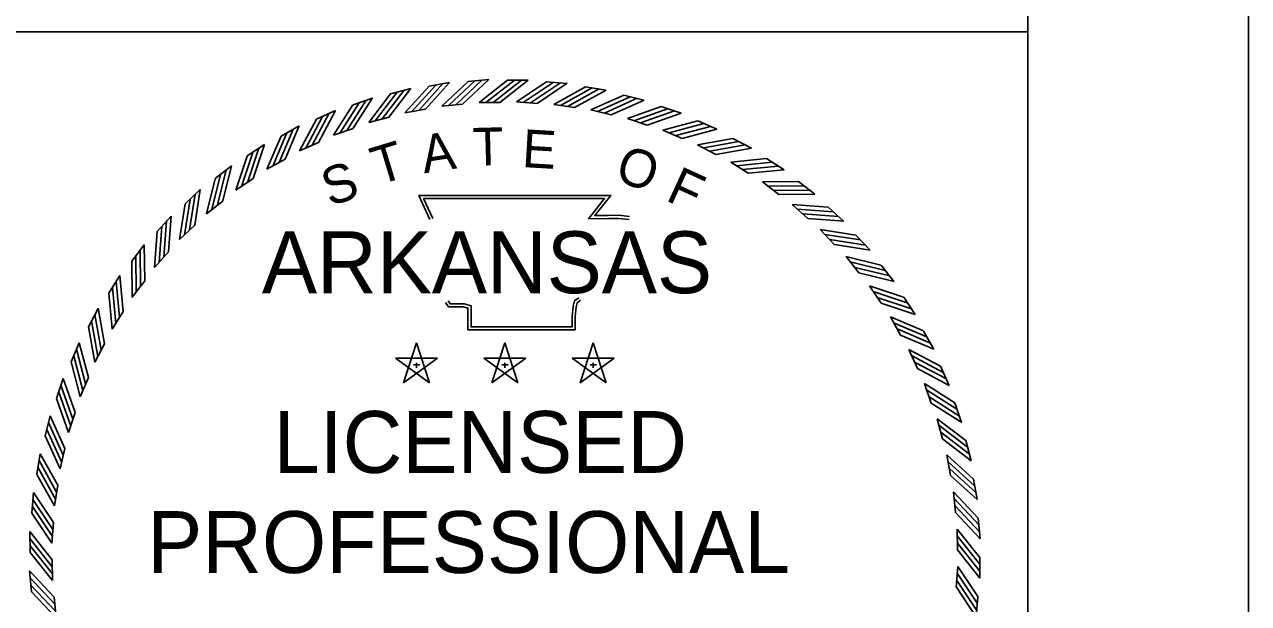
# Model space of a CAD drawing. Extents: x 0 to 1228740, y 0 to 152440.
# Drawn here: x 30.801 to 34, y 18.649 to 20.162 of the extents above; entities that cross this region are included whole.
import ezdxf

# ---------------------------------------------------------------- set-up
doc = ezdxf.new("R2010")
doc.units = 0
doc.layers.add('R_Border', color=7, linetype='Continuous')
doc.layers.add('STAMP', color=7, linetype='Continuous')

msp = doc.modelspace()

# ---------------------------------------------------------------- linework, layer by layer
at = {"layer": 'R_Border'}
for p, q in [((33.4231, 0.5768), (33.4231, 21.4232)), ((29.1131, 20.1432), (33.4231, 20.1432))]:
    msp.add_line(p, q, dxfattribs=at)
msp.add_lwpolyline([(33.9999, 22), (0, 22), (0, 0), (33.9999, 0)], close=True, dxfattribs=at)
at = {"layer": 'STAMP'}
for p, q in [((31.7579, 19.981), (31.8105, 19.9948)), ((31.8584, 20.0015), (31.912, 20.0109)), ((31.9602, 20.0137), (32.0144, 20.0186)), ((32.0633, 20.0167), (32.1177, 20.0167)), ((32.1652, 20.0126), (32.2194, 20.0086)), ((32.2669, 19.9994), (32.3206, 19.9909)), ((31.6595, 19.9522), (31.7108, 19.9703)), ((32.3671, 19.9778), (32.42, 19.965)), ((31.5637, 19.9154), (31.6134, 19.9377)), ((31.7953, 19.9316), (31.849, 19.941)), ((31.8916, 19.9492), (31.9459, 19.9542)), ((31.989, 19.9588), (32.0435, 19.9588)), ((32.0869, 19.9603), (32.1413, 19.9563)), ((32.1845, 19.9538), (32.2384, 19.9453)), ((32.2813, 19.9392), (32.3343, 19.9263)), ((32.4653, 19.9481), (32.5169, 19.9309)), ((31.7008, 19.9061), (31.7536, 19.9199)), ((32.3766, 19.9166), (32.4283, 19.8994)), ((32.5606, 19.9103), (32.6107, 19.8889)), ((31.4714, 19.8708), (31.519, 19.8972)), ((31.6088, 19.8729), (31.6602, 19.891)), ((32.4696, 19.8863), (32.5198, 19.8648)), ((31.383, 19.8188), (31.4283, 19.849)), ((31.5198, 19.8321), (31.5695, 19.8545)), ((32.5598, 19.8484), (32.608, 19.8229)), ((32.6526, 19.8648), (32.7006, 19.8393)), ((31.4344, 19.7842), (31.4821, 19.8106)), ((32.6466, 19.8031), (32.6926, 19.7737)), ((32.7404, 19.8119), (32.7862, 19.7825)), ((31.2992, 19.7596), (31.3419, 19.7934)), ((31.3533, 19.7294), (31.3987, 19.7597)), ((32.7294, 19.7509), (32.7727, 19.7178)), ((32.8235, 19.7518), (32.8668, 19.7188)), ((31.2206, 19.6937), (31.2603, 19.7309)), ((31.277, 19.6681), (31.3198, 19.702)), ((32.8076, 19.692), (32.848, 19.6554)), ((32.9015, 19.6851), (32.9418, 19.6487)), ((31.1477, 19.6216), (31.1842, 19.6619)), ((31.2061, 19.6007), (31.2459, 19.638)), ((32.8806, 19.6268), (32.9179, 19.587)), ((32.9736, 19.6123), (33.0108, 19.5726)), ((31.0811, 19.5437), (31.1141, 19.5869)), ((31.1409, 19.5277), (31.1775, 19.5681)), ((32.948, 19.5558), (32.9819, 19.5131)), ((33.0395, 19.5337), (33.0733, 19.491)), ((31.021, 19.4605), (31.0504, 19.5063)), ((31.082, 19.4495), (31.1151, 19.4928)), ((33.0093, 19.4796), (33.0396, 19.4342)), ((30.9681, 19.3727), (30.9935, 19.4207)), ((33.0987, 19.4499), (33.1288, 19.4046)), ((31.0298, 19.3667), (31.0592, 19.4127)), ((33.0641, 19.3985), (33.0905, 19.3507)), ((33.1507, 19.3615), (33.1771, 19.3139)), ((30.9226, 19.2807), (30.944, 19.3308)), ((30.9845, 19.28), (31.01, 19.3281)), ((31.8255, 19.3302), (31.7915, 19.2258)), ((31.8594, 19.2258), (31.8256, 19.3303)), ((32.0563, 19.3302), (32.0222, 19.2258)), ((32.0902, 19.2258), (32.0564, 19.3303)), ((32.2871, 19.3302), (32.253, 19.2258)), ((32.321, 19.2258), (32.2871, 19.3303)), ((31.8804, 19.2904), (31.7705, 19.2905)), ((32.1112, 19.2904), (32.0013, 19.2905)), ((32.3419, 19.2904), (32.2321, 19.2905)), ((33.112, 19.3131), (33.1344, 19.2634)), ((31.7706, 19.2904), (31.8594, 19.2257)), ((31.7916, 19.2258), (31.8805, 19.2903)), ((31.8177, 19.2728), (31.834, 19.2728)), ((31.8256, 19.2787), (31.8256, 19.2649)), ((32.0014, 19.2904), (32.0902, 19.2257)), ((32.0224, 19.2258), (32.1113, 19.2903)), ((32.0485, 19.2728), (32.0648, 19.2728)), ((32.0564, 19.2787), (32.0564, 19.2649)), ((32.2322, 19.2904), (32.321, 19.2257)), ((32.2532, 19.2258), (32.3421, 19.2903)), ((32.2793, 19.2728), (32.2956, 19.2728)), ((32.2872, 19.2787), (32.2872, 19.2649)), ((33.1953, 19.2692), (33.2176, 19.2195)), ((30.8848, 19.1854), (30.902, 19.237)), ((30.9466, 19.1897), (30.9681, 19.2399)), ((33.1528, 19.2241), (33.1709, 19.1727)), ((33.2321, 19.1734), (33.2502, 19.1221)), ((30.855, 19.0873), (30.8679, 19.1401)), ((30.9163, 19.0967), (30.9335, 19.1484)), ((33.186, 19.1321), (33.1998, 19.0793)), ((33.2608, 19.075), (33.2747, 19.0224)), ((30.8335, 18.987), (30.8419, 19.0407)), ((30.8937, 19.0014), (30.9066, 19.0544)), ((33.2115, 19.0376), (33.2209, 18.9839)), ((33.2814, 18.9745), (33.2908, 18.9209)), ((30.8203, 18.8853), (30.8243, 18.9395)), ((30.8791, 18.9046), (30.8876, 18.9585)), ((33.2291, 18.9413), (33.2341, 18.887)), ((30.8726, 18.807), (30.8766, 18.8614)), ((33.2387, 18.8439), (33.2392, 18.7893)), ((33.2936, 18.8727), (33.2985, 18.8185)), ((30.8155, 18.7828), (30.815, 18.8372)), ((30.8741, 18.7091), (30.8736, 18.7637)), ((33.2973, 18.7702), (33.2978, 18.7158)), ((30.8192, 18.6803), (30.8142, 18.7345)), ((33.2402, 18.746), (33.2362, 18.6916)), ((30.8837, 18.6117), (30.8787, 18.666)), ((33.2925, 18.6677), (33.2885, 18.6135))]:
    msp.add_line(p, q, dxfattribs=at)
for points in [[(31.7535, 19.92), (31.8106, 19.9948)], [(31.7953, 19.9315), (31.8583, 20.0014)], [(31.8126, 19.9344), (31.8756, 20.0043)], [(31.8311, 19.9381), (31.8941, 20.008)], [(31.849, 19.9411), (31.912, 20.011)], [(31.8916, 19.9491), (31.9602, 20.0136)], [(31.909, 19.9506), (31.9776, 20.015)], [(31.9278, 19.9527), (31.9964, 20.0172)], [(31.9458, 19.9542), (32.0145, 20.0187)], [(31.9889, 19.9587), (32.0632, 20.0166)], [(32.0065, 19.9586), (32.0807, 20.0165)], [(32.0254, 19.959), (32.0996, 20.0169)], [(32.0435, 19.9588), (32.1177, 20.0167)], [(32.0868, 19.9603), (32.1651, 20.0126)], [(32.1043, 19.9588), (32.1825, 20.0111)], [(32.1231, 19.9579), (32.2014, 20.0101)], [(32.1412, 19.9564), (32.2195, 20.0087)], [(32.1845, 19.9537), (32.2668, 19.9994)], [(32.2017, 19.9508), (32.2841, 19.9965)], [(31.643, 19.8852), (31.6937, 19.9645)], [(31.6601, 19.8911), (31.7108, 19.9704)], [(31.7008, 19.906), (31.7579, 19.9809)], [(31.7178, 19.9103), (31.7748, 19.9852)], [(31.7359, 19.9155), (31.793, 19.9904)], [(32.2205, 19.9483), (32.3028, 19.994)], [(32.2383, 19.9453), (32.3207, 19.991)], [(32.2812, 19.9391), (32.3671, 19.9778)], [(32.2982, 19.9348), (32.384, 19.9735)], [(32.3167, 19.9308), (32.4025, 19.9695)], [(32.3342, 19.9263), (32.4201, 19.965)], [(31.5528, 19.8472), (31.5968, 19.9305)], [(31.5694, 19.8545), (31.6134, 19.9378)], [(31.6087, 19.8728), (31.6594, 19.9521)], [(31.6253, 19.8785), (31.676, 19.9578)], [(32.3765, 19.9166), (32.4652, 19.9481)], [(32.393, 19.9109), (32.4818, 19.9424)], [(32.4111, 19.9053), (32.4998, 19.9368)], [(32.4282, 19.8994), (32.517, 19.9309)], [(31.5197, 19.8321), (31.5637, 19.9153)], [(31.5358, 19.8391), (31.5797, 19.9224)], [(32.4695, 19.8863), (32.5606, 19.9103)], [(32.4856, 19.8792), (32.5766, 19.9033)], [(31.4344, 19.7842), (31.4713, 19.8707)], [(31.4498, 19.7925), (31.4867, 19.8791)], [(31.4661, 19.802), (31.5031, 19.8886)], [(31.4821, 19.8106), (31.519, 19.8972)], [(32.5031, 19.8722), (32.5941, 19.8962)], [(32.5197, 19.8649), (32.6107, 19.8889)], [(31.3835, 19.7498), (31.4131, 19.8391)], [(31.3986, 19.7597), (31.4283, 19.849)], [(32.5598, 19.8483), (32.6525, 19.8648)], [(32.5752, 19.84), (32.6679, 19.8565)], [(32.5921, 19.8315), (32.6848, 19.848)], [(32.608, 19.8229), (32.7007, 19.8394)], [(31.3533, 19.7293), (31.383, 19.8187)], [(31.368, 19.7389), (31.3976, 19.8283)], [(32.6466, 19.8031), (32.7403, 19.8119)], [(32.6612, 19.7935), (32.755, 19.8023)], [(31.2908, 19.6788), (31.313, 19.7703)], [(31.3054, 19.6909), (31.3276, 19.7823)], [(31.3197, 19.702), (31.3419, 19.7935)], [(32.6774, 19.7837), (32.7711, 19.7924)], [(32.6925, 19.7738), (32.7863, 19.7825)], [(31.277, 19.668), (31.2992, 19.7595)], [(32.7293, 19.7509), (32.8235, 19.7518)], [(32.7431, 19.7401), (32.8373, 19.7411)], [(31.2324, 19.6257), (31.247, 19.7187)], [(31.2458, 19.638), (31.2603, 19.731)], [(31.8606, 19.6525), (31.8316, 19.7154), (32.3333, 19.7156), (32.2914, 19.663), (32.3255, 19.6634), (32.354, 19.6638), (32.3824, 19.6607)], [(31.8678, 19.6559), (31.844, 19.7074), (32.3169, 19.7077), (32.2748, 19.6548), (32.3256, 19.6555), (32.3536, 19.6558), (32.3816, 19.6528)], [(32.7584, 19.729), (32.8526, 19.7299)], [(32.7727, 19.7179), (32.8669, 19.7188)], [(31.2061, 19.6006), (31.2206, 19.6936)], [(31.2189, 19.6125), (31.2335, 19.7055)], [(32.8075, 19.692), (32.9014, 19.6852)], [(32.8204, 19.6801), (32.9143, 19.6733)], [(31.1651, 19.5548), (31.172, 19.6487)], [(31.1774, 19.5681), (31.1842, 19.662)], [(32.8347, 19.6678), (32.9286, 19.6609)], [(32.848, 19.6555), (32.9419, 19.6487)], [(31.1409, 19.5276), (31.1477, 19.6215)], [(31.1528, 19.5405), (31.1596, 19.6344)], [(32.8805, 19.6268), (32.9735, 19.6123)], [(32.8924, 19.6139), (32.9854, 19.5994)], [(31.115, 19.4928), (31.1141, 19.587)], [(32.9056, 19.6004), (32.9986, 19.5859)], [(32.9179, 19.5871), (33.0109, 19.5726)], [(31.0928, 19.4632), (31.0918, 19.5574)], [(31.1039, 19.4785), (31.1029, 19.5727)], [(32.9479, 19.5559), (33.0394, 19.5337)], [(31.082, 19.4494), (31.0811, 19.5436)], [(32.9587, 19.542), (33.0502, 19.5199)], [(32.9708, 19.5275), (33.0622, 19.5053)], [(31.0492, 19.3975), (31.0405, 19.4912)], [(31.0591, 19.4126), (31.0504, 19.5064)], [(32.9819, 19.5132), (33.0734, 19.491)], [(31.0298, 19.3667), (31.021, 19.4604)], [(31.0393, 19.3813), (31.0306, 19.4751)], [(33.0092, 19.4796), (33.0986, 19.4499)], [(33.0188, 19.4649), (33.1082, 19.4353)], [(31.01, 19.3281), (30.9935, 19.4208)], [(32.2543, 19.4423), (32.2457, 19.4353), (32.2429, 19.4249), (32.24, 19.3989), (32.24, 19.3642), (31.9599, 19.3642), (31.9599, 19.411), (31.9599, 19.4214), (31.9486, 19.4249), (31.9087, 19.4249), (31.9016, 19.4357)], [(32.2493, 19.4484), (32.2387, 19.4399), (32.235, 19.4264), (32.2321, 19.3993), (32.2321, 19.3721), (31.9679, 19.3721), (31.9679, 19.411), (31.9679, 19.4273), (31.9497, 19.4328), (31.913, 19.4328), (31.9083, 19.4401)], [(33.0296, 19.4494), (33.119, 19.4198)], [(33.0396, 19.4343), (33.1289, 19.4046)], [(30.9929, 19.2953), (30.9764, 19.388)], [(31.0013, 19.3122), (30.9849, 19.4049)], [(33.064, 19.3985), (33.1506, 19.3616)], [(30.9845, 19.2799), (30.9681, 19.3726)], [(33.0724, 19.3831), (33.159, 19.3462)], [(33.0819, 19.3668), (33.1685, 19.3298)], [(30.968, 19.2398), (30.944, 19.3308)], [(33.0905, 19.3508), (33.1771, 19.3139)], [(30.9537, 19.2057), (30.9296, 19.2967)], [(30.9607, 19.2232), (30.9367, 19.3142)], [(33.112, 19.3132), (33.1952, 19.2692)], [(33.119, 19.2971), (33.2023, 19.2532)], [(30.9466, 19.1896), (30.9226, 19.2807)], [(33.1271, 19.2801), (33.2104, 19.2361)], [(33.1344, 19.2635), (33.2177, 19.2195)], [(30.9335, 19.1484), (30.902, 19.2371)], [(30.922, 19.1131), (30.8905, 19.2019)], [(30.9276, 19.1312), (30.8961, 19.2199)], [(33.1527, 19.2242), (33.232, 19.1735)], [(33.1584, 19.2076), (33.2377, 19.1569)], [(30.9163, 19.0966), (30.8848, 19.1853)], [(33.1651, 19.1899), (33.2444, 19.1392)], [(33.1709, 19.1728), (33.2503, 19.1221)], [(30.9066, 19.0544), (30.8679, 19.1402)], [(33.1859, 19.1321), (33.2608, 19.075)], [(30.8981, 19.0183), (30.8594, 19.1041)], [(30.9021, 19.0368), (30.8634, 19.1226)], [(33.1902, 19.1151), (33.2651, 19.0581)], [(30.8938, 19.0013), (30.8551, 19.0872)], [(33.1954, 19.097), (33.2703, 19.0399)], [(33.1999, 19.0794), (33.2747, 19.0223)], [(30.8876, 18.9585), (30.8419, 19.0408)], [(33.2114, 19.0376), (33.2813, 18.9746)], [(30.8821, 18.9218), (30.8364, 19.0042)], [(30.8846, 18.9406), (30.8389, 19.0229)], [(33.2143, 19.0203), (33.2842, 18.9573)], [(30.8792, 18.9046), (30.8335, 18.9869)], [(33.218, 19.0018), (33.2879, 18.9387)], [(33.221, 18.9839), (33.2909, 18.9209)], [(30.8765, 18.8613), (30.8242, 18.9396)], [(33.229, 18.9413), (33.2935, 18.8727)], [(30.875, 18.8432), (30.8227, 18.9215)], [(33.2305, 18.9239), (33.2949, 18.8553)], [(30.8726, 18.8069), (30.8203, 18.8852)], [(30.8741, 18.8244), (30.8218, 18.9026)], [(33.2326, 18.9051), (33.2971, 18.8365)], [(33.2341, 18.887), (33.2986, 18.8184)], [(33.2386, 18.8439), (33.2972, 18.7702)], [(30.8736, 18.7636), (30.815, 18.8373)], [(30.8736, 18.7455), (30.815, 18.8192)], [(33.2386, 18.8264), (33.2972, 18.7527)], [(30.8741, 18.7266), (30.8156, 18.8003)], [(30.8741, 18.7091), (30.8156, 18.7828)], [(33.2392, 18.8075), (33.2978, 18.7338)], [(33.2392, 18.7894), (33.2978, 18.7157)], [(30.8787, 18.666), (30.8142, 18.7346)], [(30.8802, 18.6479), (30.8157, 18.7165)], [(33.2387, 18.7286), (33.291, 18.6503)], [(33.2402, 18.7461), (33.2925, 18.6678)], [(30.8823, 18.6291), (30.8178, 18.6977)], [(33.2363, 18.6917), (33.2885, 18.6134)], [(33.2378, 18.7098), (33.29, 18.6315)], [(30.8838, 18.6117), (30.8193, 18.6803)]]:
    msp.add_lwpolyline(points, dxfattribs=at)

# ---------------------------------------------------------------- texts
for s, rotation, p in [('A', 8.6788, (31.8453, 19.7733)), ('T', 1.4789, (31.9731, 19.793)), ('E', 356.672, (32.0998, 19.79)), ('T', 16.9015, (31.7251, 19.742)), ('O', 341.2218, (32.3401, 19.7561)), ('S', 19.7726, (31.5992, 19.6855)), ('F', 335.3628, (32.4735, 19.7039))]:
    msp.add_text(s, height=0.099, rotation=rotation, dxfattribs=at).set_placement(p)
for s, height, p in [('ARKANSAS', 0.16155, (31.4214, 19.4603)), ('LICENSED', 0.16155, (31.4521, 18.9908)), ('PROFESSIONAL', 0.161547, (31.1214, 18.7292))]:
    msp.add_text(s, height=height, dxfattribs=at).set_placement(p)

doc.saveas('drawing.dxf')
